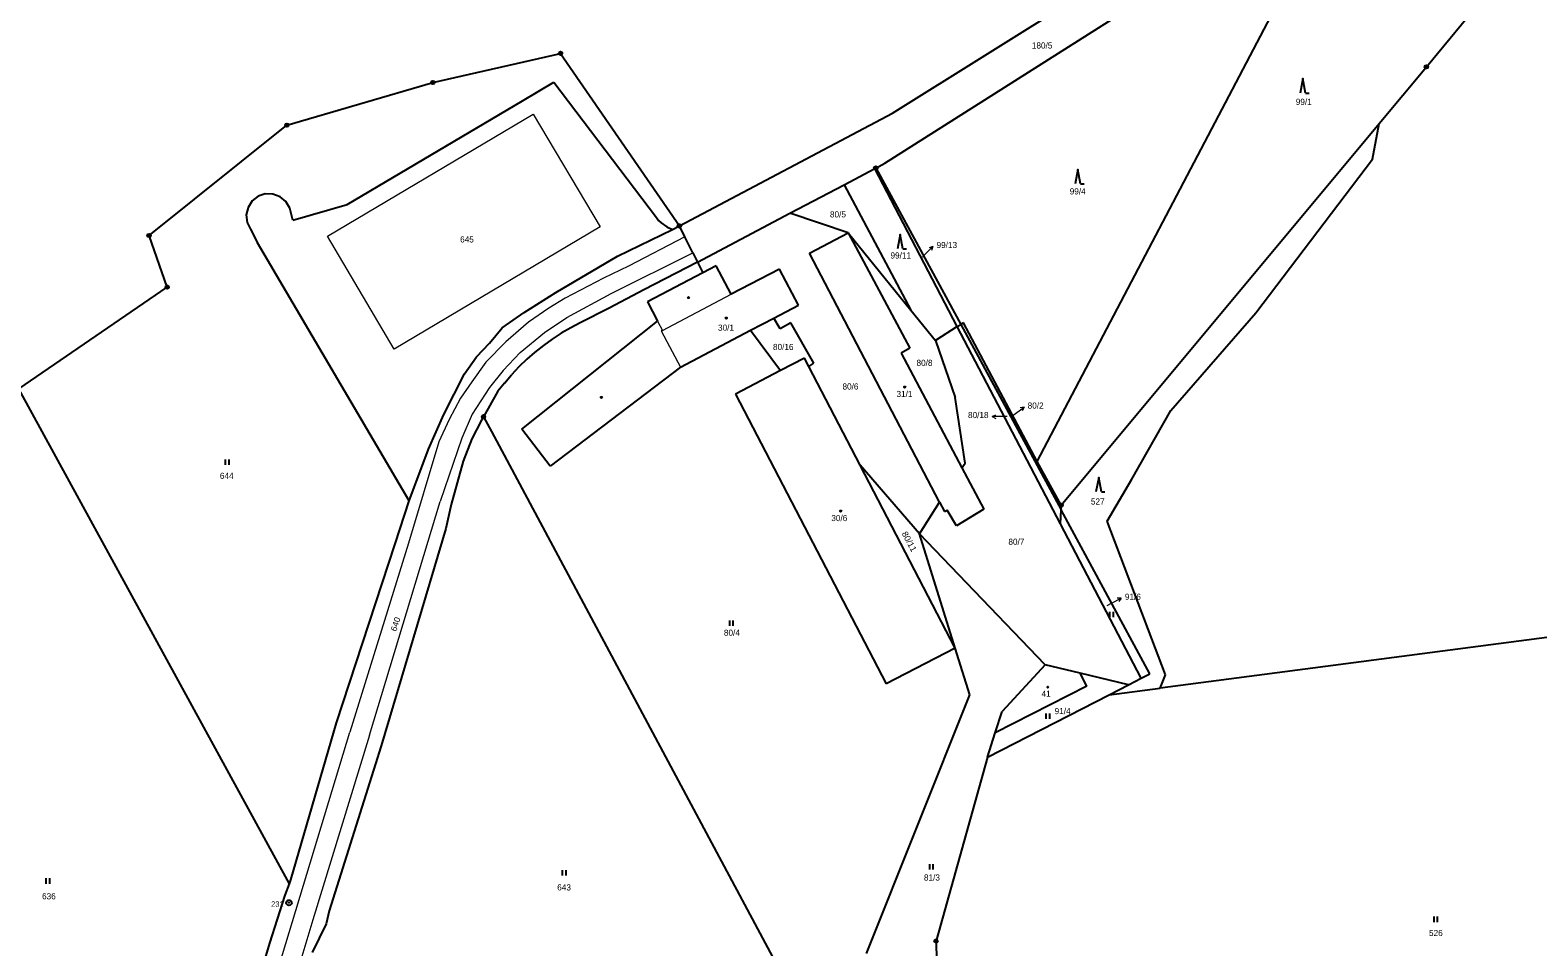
# Model space of a CAD drawing. Extents: x -653193 to -651624, y -1092017 to -1090260.
# Drawn here: x -652826.7 to -652409.3, y -1091115.4 to -1090861.4 of the extents above; entities that cross this region are included whole.
import ezdxf
from ezdxf.enums import TextEntityAlignment as Align

# ---------------------------------------------------------------- set-up
doc = ezdxf.new("R2010")
doc.units = 0
doc.header["$LTSCALE"] = 0.68
for name, color, linetype, lineweight in [('1', 7, 'Continuous', 25), ('3', 7, 'Continuous', 25), ('4', 7, 'Continuous', 13), ('5', 7, 'Continuous', 25), ('7', 7, 'Continuous', 13), ('8', 7, 'Continuous', 25)]:
    doc.layers.add(name, color=color, linetype=linetype, lineweight=lineweight)
doc.layers.add('2', color=7, linetype='Continuous')

msp = doc.modelspace()

# ---------------------------------------------------------------- linework, layer by layer
at = {"layer": '1'}
for p, q in [((-652587.98, -1090884.44), (-652455.47, -1090801.44)), ((-652590.07, -1090898.28), (-652461.88, -1090816.92)), ((-652547.89, -1090980.88), (-652461.88, -1090816.92)), ((-652440.11, -1090871.57), (-652398.57, -1090821.14)), ((-652715.24, -1090875.91), (-652679.86, -1090867.84)), ((-652679.86, -1090867.84), (-652646.95, -1090915.64)), ((-652453.21, -1090887.3), (-652440.11, -1090871.57)), ((-652755.67, -1090887.72), (-652715.24, -1090875.91)), ((-652690.37, -1090880.97), (-652681.74, -1090875.82)), ((-652681.74, -1090875.82), (-652653.34, -1090913.35)), ((-652738.99, -1090909.75), (-652690.37, -1090880.97)), ((-652793.82, -1090918.29), (-652755.67, -1090887.72)), ((-652646.95, -1090915.64), (-652587.98, -1090884.44)), ((-652541.25, -1090993.04), (-652453.21, -1090887.3)), ((-652455.06, -1090897.17), (-652453.21, -1090887.3)), ((-652601.37, -1090904.23), (-652592.89, -1090899.75)), ((-652592.89, -1090899.75), (-652592.6, -1090899.6)), ((-652570.04, -1090943.47), (-652592.89, -1090899.75)), ((-652592.6, -1090899.6), (-652590.07, -1090898.28)), ((-652592.6, -1090899.6), (-652591.89, -1090900.78)), ((-652487.35, -1090939.76), (-652455.06, -1090897.17)), ((-652616.35, -1090912.15), (-652601.37, -1090904.23)), ((-652601.37, -1090904.23), (-652582.85, -1090939.01)), ((-652591.89, -1090900.78), (-652569.07, -1090942.94)), ((-652765.29, -1090908.72), (-652766.41, -1090910.5)), ((-652763.64, -1090907.44), (-652765.29, -1090908.72)), ((-652761.63, -1090906.79), (-652763.64, -1090907.44)), ((-652759.53, -1090906.83), (-652761.63, -1090906.79)), ((-652757.56, -1090907.55), (-652759.53, -1090906.83)), ((-652755.95, -1090908.91), (-652757.56, -1090907.55)), ((-652766.41, -1090910.5), (-652766.9, -1090912.55)), ((-652766.9, -1090912.55), (-652766.65, -1090914.65)), ((-652754.85, -1090910.68), (-652755.95, -1090908.91)), ((-652754.01, -1090914.01), (-652754.85, -1090910.68)), ((-652754.01, -1090914.01), (-652738.99, -1090909.75)), ((-652641.94, -1090925.67), (-652616.35, -1090912.15)), ((-652600.2, -1090917.53), (-652616.35, -1090912.15)), ((-652766.65, -1090914.65), (-652765.77, -1090916.56)), ((-652765.77, -1090916.56), (-652763.77, -1090920.28)), ((-652664.14, -1090924.04), (-652648.92, -1090916.61)), ((-652653.34, -1090913.35), (-652652.76, -1090914.11)), ((-652652.76, -1090914.11), (-652652.06, -1090914.8)), ((-652652.06, -1090914.8), (-652650.49, -1090915.92)), ((-652650.49, -1090915.92), (-652648.92, -1090916.61)), ((-652648.92, -1090916.61), (-652646.95, -1090915.64)), ((-652645.44, -1090918.66), (-652646.95, -1090915.64)), ((-652788.81, -1090932.56), (-652793.82, -1090918.29)), ((-652721.82, -1090991.83), (-652763.77, -1090920.28)), ((-652643.25, -1090923.05), (-652645.44, -1090918.66)), ((-652610.97, -1090923.16), (-652600.2, -1090917.53)), ((-652600.2, -1090917.53), (-652583.19, -1090949.48)), ((-652600.2, -1090917.53), (-652582.85, -1090939.01)), ((-652681.14, -1090934.06), (-652664.14, -1090924.04)), ((-652643.25, -1090923.05), (-652641.94, -1090925.67)), ((-652574.9, -1090992.16), (-652610.97, -1090923.16)), ((-652641.94, -1090925.67), (-652656.79, -1090933.37)), ((-652640.46, -1090928.61), (-652655.84, -1090936.66)), ((-652641.94, -1090925.67), (-652640.46, -1090928.61)), ((-652636.77, -1090926.67), (-652640.46, -1090928.61)), ((-652632.62, -1090934.58), (-652636.77, -1090926.67)), ((-652619.27, -1090927.59), (-652632.62, -1090934.58)), ((-652614.03, -1090937.62), (-652619.27, -1090927.59)), ((-652829.92, -1090960.77), (-652788.81, -1090932.56)), ((-652656.79, -1090933.37), (-652666.44, -1090938.4)), ((-652689.99, -1090939.65), (-652681.14, -1090934.06)), ((-652655.84, -1090936.66), (-652653.04, -1090942.01)), ((-652620.83, -1090941.19), (-652614.03, -1090937.62)), ((-652696.01, -1090943.88), (-652689.99, -1090939.65)), ((-652690.62, -1090971.9), (-652653.04, -1090942.01)), ((-652666.44, -1090938.4), (-652674.43, -1090942.45)), ((-652627.26, -1090944.56), (-652620.83, -1090941.19)), ((-652619.05, -1090944.19), (-652620.83, -1090941.19)), ((-652582.85, -1090939.01), (-652576.08, -1090947.38)), ((-652510.87, -1090966.74), (-652487.35, -1090939.76)), ((-652699.57, -1090948.11), (-652696.01, -1090943.88)), ((-652679.71, -1090945.38), (-652682.22, -1090946.99)), ((-652677.07, -1090943.85), (-652679.71, -1090945.38)), ((-652674.43, -1090942.45), (-652677.07, -1090943.85)), ((-652646.66, -1090954.74), (-652627.26, -1090944.56)), ((-652627.26, -1090944.56), (-652618.97, -1090955.69)), ((-652616.15, -1090942.51), (-652619.05, -1090944.19)), ((-652609.71, -1090953.69), (-652616.15, -1090942.51)), ((-652570.04, -1090943.47), (-652576.08, -1090947.38)), ((-652570.04, -1090943.47), (-652569.07, -1090942.94)), ((-652541.43, -1090998.2), (-652570.04, -1090943.47)), ((-652568.31, -1090942.52), (-652569.07, -1090942.94)), ((-652569.07, -1090942.94), (-652541.29, -1090994.26)), ((-652547.89, -1090980.88), (-652568.31, -1090942.52)), ((-652703.16, -1090951.86), (-652699.57, -1090948.11)), ((-652684.63, -1090948.78), (-652687.06, -1090950.69)), ((-652682.22, -1090946.99), (-652684.63, -1090948.78)), ((-652583.19, -1090949.48), (-652585.58, -1090950.89)), ((-652576.08, -1090947.38), (-652570.64, -1090963.2)), ((-652706.46, -1090956.59), (-652703.16, -1090951.86)), ((-652691.4, -1090954.72), (-652693.48, -1090956.91)), ((-652689.2, -1090952.58), (-652691.4, -1090954.72)), ((-652687.06, -1090950.69), (-652689.2, -1090952.58)), ((-652646.66, -1090954.74), (-652682.76, -1090982.23)), ((-652612.37, -1090952.23), (-652618.97, -1090955.69)), ((-652611.17, -1090954.54), (-652612.37, -1090952.23)), ((-652611.17, -1090954.54), (-652609.71, -1090953.69)), ((-652596.92, -1090981.96), (-652611.17, -1090954.54)), ((-652585.58, -1090950.89), (-652568.75, -1090982.67)), ((-652712.16, -1090967.85), (-652706.46, -1090956.59)), ((-652695.4, -1090959.18), (-652693.48, -1090956.91)), ((-652618.97, -1090955.69), (-652631.43, -1090962.21)), ((-652754.93, -1091097.89), (-652829.92, -1090960.77)), ((-652697.2, -1090961.46), (-652701.21, -1090968.5)), ((-652695.4, -1090959.18), (-652697.2, -1090961.46)), ((-652631.43, -1090962.21), (-652589.68, -1091042.51)), ((-652567.83, -1090981.34), (-652570.64, -1090963.2)), ((-652521.64, -1090985.84), (-652510.87, -1090966.74)), ((-652716.4, -1090977.51), (-652712.16, -1090967.85)), ((-652701.74, -1090969.43), (-652704.44, -1090974.64)), ((-652701.21, -1090968.5), (-652701.74, -1090969.43)), ((-652701.21, -1090968.5), (-652699, -1090972.63)), ((-652704.44, -1090974.64), (-652706.86, -1090980.78)), ((-652699, -1090972.63), (-652607.81, -1091143.07)), ((-652682.76, -1090982.23), (-652690.62, -1090971.9)), ((-652721.82, -1090991.83), (-652716.4, -1090977.51)), ((-652706.86, -1090980.78), (-652710.19, -1090992.86)), ((-652580.51, -1091000.95), (-652596.92, -1090981.96)), ((-652570.61, -1091032.57), (-652596.92, -1090981.96)), ((-652568.75, -1090982.67), (-652567.83, -1090981.34)), ((-652568.75, -1090982.67), (-652562.7, -1090994.11)), ((-652541.25, -1090993.04), (-652547.89, -1090980.88)), ((-652528.52, -1090997.46), (-652521.64, -1090985.84)), ((-652725.71, -1091003.67), (-652721.82, -1090991.83)), ((-652580.51, -1091000.95), (-652574.9, -1090992.16)), ((-652574.9, -1090992.16), (-652573.56, -1090994.73)), ((-652710.19, -1090992.86), (-652711.66, -1090999.46)), ((-652573.56, -1090994.73), (-652572.83, -1090994.35)), ((-652570.23, -1090998.69), (-652572.83, -1090994.35)), ((-652562.7, -1090994.11), (-652570.23, -1090998.69)), ((-652541.43, -1090998.2), (-652541.29, -1090994.26)), ((-652541.29, -1090994.26), (-652541.25, -1090993.04)), ((-652516.66, -1091039.77), (-652541.29, -1090994.26)), ((-652711.66, -1090999.46), (-652729.56, -1091059.71)), ((-652519.08, -1091040.96), (-652541.43, -1090998.2)), ((-652512.35, -1091040.01), (-652528.52, -1090997.46)), ((-652741.91, -1091053.27), (-652725.71, -1091003.67)), ((-652570.61, -1091032.57), (-652580.51, -1091000.95)), ((-652545.71, -1091037.22), (-652580.51, -1091000.95)), ((-652406.81, -1091029.7), (-652513.84, -1091043.71)), ((-652570.61, -1091032.57), (-652589.68, -1091042.51)), ((-652566.54, -1091045.56), (-652570.61, -1091032.57)), ((-652545.71, -1091037.22), (-652557.62, -1091050.16)), ((-652535.96, -1091039.56), (-652545.71, -1091037.22)), ((-652534.17, -1091043.11), (-652535.96, -1091039.56)), ((-652522.58, -1091042.76), (-652535.96, -1091039.56)), ((-652522.58, -1091042.76), (-652519.08, -1091040.96)), ((-652519.08, -1091040.96), (-652516.66, -1091039.77)), ((-652513.84, -1091043.71), (-652512.35, -1091040.01)), ((-652595.19, -1091117.19), (-652566.54, -1091045.56)), ((-652561.65, -1091062.79), (-652527.94, -1091045.51)), ((-652534.17, -1091043.11), (-652559.5, -1091056.04)), ((-652527.94, -1091045.51), (-652522.58, -1091042.76)), ((-652527.94, -1091045.51), (-652513.84, -1091043.71)), ((-652559.5, -1091056.04), (-652557.62, -1091050.16)), ((-652754.52, -1091096.82), (-652741.91, -1091053.27)), ((-652561.65, -1091062.79), (-652559.5, -1091056.04)), ((-652729.56, -1091059.71), (-652743.95, -1091105.35)), ((-652561.65, -1091062.79), (-652575.91, -1091113.74)), ((-652756.13, -1091101.04), (-652754.93, -1091097.89)), ((-652754.93, -1091097.89), (-652754.52, -1091096.82)), ((-652760.41, -1091114.3), (-652756.13, -1091101.04)), ((-652744.81, -1091109), (-652748.62, -1091116.93)), ((-652743.95, -1091105.35), (-652744.81, -1091109)), ((-652765.2, -1091130.77), (-652760.41, -1091114.3)), ((-652575.91, -1091113.74), (-652575.59, -1091127.97))]:
    msp.add_line(p, q, dxfattribs=at)
at = {"layer": '3'}
for p, q in [((-652473.55, -1090878.82), (-652472.554, -1090878.82)), ((-652535.92, -1090903.99), (-652534.924, -1090903.99)), ((-652585.1, -1090922.02), (-652584.104, -1090922.02)), ((-652772.641, -1090981.83), (-652772.641, -1090980.33)), ((-652771.64, -1090981.83), (-652771.64, -1090980.33)), ((-652530.11, -1090989.32), (-652529.114, -1090989.32)), ((-652633.041, -1091026.42), (-652633.041, -1091024.92)), ((-652632.04, -1091026.42), (-652632.04, -1091024.92)), ((-652527.751, -1091024.04), (-652527.751, -1091022.54)), ((-652526.75, -1091024.04), (-652526.75, -1091022.54)), ((-652545.391, -1091052.21), (-652545.391, -1091050.71)), ((-652544.39, -1091052.21), (-652544.39, -1091050.71)), ((-652577.651, -1091093.93), (-652577.651, -1091092.43)), ((-652576.65, -1091093.93), (-652576.65, -1091092.43)), ((-652822.271, -1091097.88), (-652822.271, -1091096.38)), ((-652821.27, -1091097.88), (-652821.27, -1091096.38)), ((-652679.361, -1091095.61), (-652679.361, -1091094.11)), ((-652678.36, -1091095.61), (-652678.36, -1091094.11)), ((-652438.001, -1091108.5), (-652438.001, -1091107)), ((-652437, -1091108.5), (-652437, -1091107))]:
    msp.add_line(p, q, dxfattribs=at)
for points in [[(-652473.55, -1090878.82), (-652474.3, -1090874.82), (-652475.05, -1090878.82)], [(-652535.92, -1090903.99), (-652536.67, -1090899.99), (-652537.42, -1090903.99)], [(-652585.1, -1090922.02), (-652585.85, -1090918.02), (-652586.6, -1090922.02)], [(-652530.11, -1090989.32), (-652530.86, -1090985.32), (-652531.61, -1090989.32)]]:
    msp.add_lwpolyline(points, dxfattribs=at)
at = {"layer": '4'}
for p, q in [((-652744.37, -1090918.44), (-652687.44, -1090884.69)), ((-652687.44, -1090884.69), (-652668.86, -1090915.88)), ((-652668.86, -1090915.88), (-652725.92, -1090949.82)), ((-652725.92, -1090949.82), (-652744.37, -1090918.44)), ((-652645.44, -1090918.66), (-652661.02, -1090926.75)), ((-652665.83, -1090934.4), (-652643.25, -1090923.05)), ((-652661.02, -1090926.75), (-652668.02, -1090930.13)), ((-652668.02, -1090930.13), (-652678.62, -1090935.66)), ((-652678.62, -1090935.66), (-652683.16, -1090938.41)), ((-652678.12, -1090941.05), (-652665.83, -1090934.4)), ((-652651.69, -1090944.57), (-652632.62, -1090934.58)), ((-652683.16, -1090938.41), (-652688.75, -1090942.32)), ((-652684.35, -1090945.13), (-652678.12, -1090941.05)), ((-652653.04, -1090942.01), (-652651.69, -1090944.57)), ((-652688.75, -1090942.32), (-652695.02, -1090947.75)), ((-652691.05, -1090950.66), (-652684.35, -1090945.13)), ((-652651.69, -1090944.57), (-652652, -1090944.68)), ((-652652, -1090944.68), (-652646.66, -1090954.74)), ((-652695.02, -1090947.75), (-652700.55, -1090953.41)), ((-652700.55, -1090953.41), (-652704.47, -1090958.86)), ((-652691.05, -1090950.66), (-652695.81, -1090955.73)), ((-652704.47, -1090958.86), (-652707.61, -1090963.33)), ((-652695.81, -1090955.73), (-652699.55, -1090960.38)), ((-652699.55, -1090960.38), (-652704.32, -1090967.8)), ((-652707.61, -1090963.33), (-652710.7, -1090969.25)), ((-652710.7, -1090969.25), (-652713.54, -1090975.41)), ((-652704.32, -1090967.8), (-652707.19, -1090974.45)), ((-652713.54, -1090975.41), (-652722.02, -1091003.55)), ((-652707.19, -1090974.45), (-652713.2, -1090991.96)), ((-652732.77, -1091056.7), (-652713.2, -1090991.96)), ((-652722.02, -1091003.55), (-652738.2, -1091055.88)), ((-652761.59, -1091133.01), (-652738.2, -1091055.88)), ((-652732.77, -1091056.7), (-652748.48, -1091107.9)), ((-652748.48, -1091107.9), (-652756.82, -1091135.86))]:
    msp.add_line(p, q, dxfattribs=at)
at = {"layer": '5'}
for centre in [(-652644.4568, -1090935.4992), (-652633.9868, -1090941.1692), (-652668.5668, -1090963.1492), (-652584.5568, -1090960.2792), (-652602.2968, -1090994.6392), (-652544.9468, -1091043.4092)]:
    msp.add_circle(centre, 0.175, dxfattribs=at)
at = {"layer": '7'}
for p, q in [((-652576.758, -1090921.348), (-652577.82, -1090921.702)), ((-652551.523, -1090965.844), (-652552.624, -1090966.047)), ((-652560.361, -1090968.45), (-652559.36, -1090968.951)), ((-652524.606, -1091018.768), (-652525.726, -1091018.776))]:
    msp.add_line(p, q, dxfattribs=at)
for points in [[(-652579.68, -1090924.27), (-652578.88, -1090923.47), (-652576.758, -1090921.348), (-652577.112, -1090922.41)], [(-652554.89, -1090968.38), (-652553.92, -1090967.65), (-652551.523, -1090965.844), (-652552.022, -1090966.847)], [(-652556.23, -1090968.45), (-652557.36, -1090968.45), (-652560.361, -1090968.45), (-652559.36, -1090967.949)], [(-652528.52, -1091020.75), (-652527.28, -1091020.13), (-652524.606, -1091018.768), (-652525.271, -1091019.668)]]:
    msp.add_lwpolyline(points, dxfattribs=at)
at = {"layer": '8'}
for centre, radius in [((-652679.86, -1090867.8399), 0.5), ((-652679.86, -1090867.8399), 0.0303), ((-652440.11, -1090871.5699), 0.5), ((-652715.24, -1090875.9099), 0.5), ((-652440.11, -1090871.5699), 0.0303), ((-652715.24, -1090875.9099), 0.0303), ((-652755.67, -1090887.7199), 0.5), ((-652755.67, -1090887.7199), 0.0303), ((-652592.6, -1090899.5999), 0.5), ((-652592.6, -1090899.5999), 0.0303), ((-652646.95, -1090915.6399), 0.5), ((-652646.95, -1090915.6399), 0.0303), ((-652793.82, -1090918.2899), 0.5), ((-652793.82, -1090918.2899), 0.0303), ((-652788.81, -1090932.5599), 0.5), ((-652788.81, -1090932.5599), 0.0303), ((-652701.21, -1090968.4999), 0.5), ((-652701.21, -1090968.4999), 0.0303), ((-652541.25, -1090993.0399), 0.5), ((-652541.25, -1090993.0399), 0.0303), ((-652755.07, -1091103.1398), 0.75), ((-652755.07, -1091103.1398), 0.03), ((-652575.91, -1091113.7399), 0.5), ((-652575.91, -1091113.7399), 0.0303)]:
    msp.add_circle(centre, radius, dxfattribs=at)

# ---------------------------------------------------------------- texts
at = {"layer": '2'}
for s, p in [('180/5', (-652546.52, -1090866.495)), ('99/1', (-652474.069, -1090882.115)), ('99/4', (-652536.669, -1090906.915)), ('80/5', (-652603.059, -1090913.285)), ('645', (-652705.789, -1090920.225)), ('99/11', (-652585.67, -1090924.675)), ('30/1', (-652634.059, -1090944.675)), ('80/16', (-652618.21, -1090950.025)), ('80/8', (-652579.089, -1090954.425)), ('80/6', (-652599.589, -1090960.965)), ('31/1', (-652584.629, -1090963.045)), ('644', (-652772.309, -1090985.715)), ('527', (-652531.119, -1090992.835)), ('30/6', (-652602.689, -1090997.415)), ('80/7', (-652553.649, -1091003.985)), ('80/4', (-652632.429, -1091029.195)), ('41', (-652545.429, -1091046.095)), ('91/4', (-652540.849, -1091050.895)), ('81/3', (-652577.039, -1091096.995)), ('636', (-652821.549, -1091102.205)), ('643', (-652678.899, -1091099.735)), ('526', (-652437.499, -1091112.375))]:
    msp.add_text(s, height=1.7, dxfattribs=at).set_placement(p, align=Align.CENTER)
for s, p in [('99/13', (-652575.76, -1090921.775)), ('80/2', (-652550.53, -1090966.265)), ('91/6', (-652523.6, -1091019.215))]:
    msp.add_text(s, height=1.7, dxfattribs=at).set_placement(p)
msp.add_text('80/18', height=1.7, dxfattribs=at).set_placement((-652561.36, -1090968.875), align=Align.RIGHT)
at = {"layer": '2', "width": 1.05}
for s, rotation, p in [('80/11', 298, (-652584.0564, -1091003.4724)), ('640', 72, (-652724.7521, -1091026.2267))]:
    msp.add_text(s, height=1.7, rotation=rotation, dxfattribs=at).set_placement(p, align=Align.CENTER)
at = {"layer": '8'}
msp.add_text('231', height=1.5, dxfattribs=at).set_placement((-652756.569, -1091104.257), align=Align.RIGHT)

doc.saveas('drawing.dxf')
